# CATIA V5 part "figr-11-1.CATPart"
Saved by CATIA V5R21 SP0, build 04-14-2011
Part number: Part1
Bounding box of the stored display mesh (mm): x -50 to 50, y -98.731 to 72.975, z 0 to 120
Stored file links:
  D:\CATIA V5R21 E-RESOURCES\CATIA-V5R21\catia-v5r21-prt\c11-catia-v5r21-prt\c11-catia-v5r21-figr-11-1.CATPart
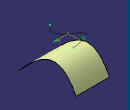
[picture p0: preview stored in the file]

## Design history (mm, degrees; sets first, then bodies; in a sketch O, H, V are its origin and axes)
Set1
  Sketch1 on yz-plane, origin (0, 0, 0), H (0, 1, 0), V (0, 0, 1)
    spline S1 through (-98.7309, 0) (-73.2816, 27.1192) (0, 74.8227) (72.975, 18.624)
    point P1 (-98.7309, 0)
    point P2 (0, 74.8227)
    coincidence: P1 H, P2 V
  Extrude1: Element1 Sketch1, Lim1 50, Lim2 50, Direction yz-plane
  Plane1: type Offset, RefPlane xy-plane, Offset 120
  Sketch2 on Plane1, origin (0, 0, 120), H (1, 0, 0), V (0, 1, 0)
    spline S1 through (28.7787, 44.6229) (-22.3035, 19.7059) (20.5049, -22.8447) (5.396, -48.9118)
Body1 (main body)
